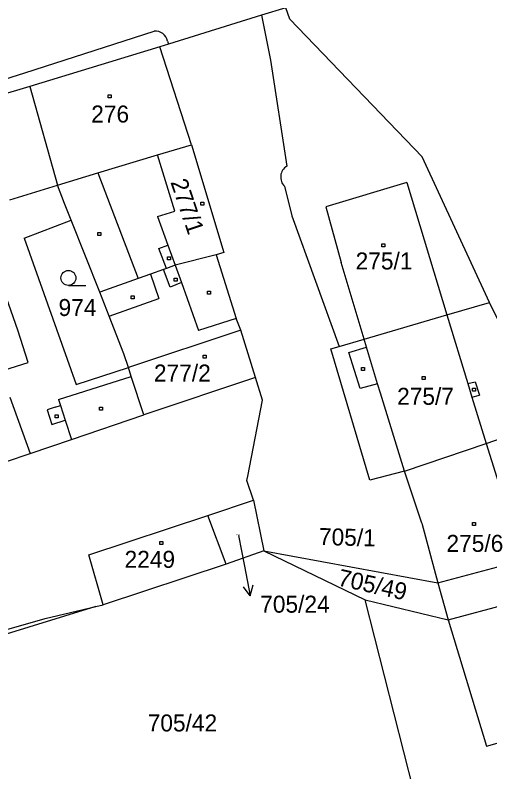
# Model space of a CAD drawing. Extents: x -711879 to -711361, y -1048782 to -1048177.
# Drawn here: x -711605.1 to -711557.6, y -1048600.7 to -1048524.9 of the extents above; entities that cross this region are included whole.
import ezdxf

# ---------------------------------------------------------------- set-up
doc = ezdxf.new("R2010")
doc.units = 0
for name, color, linetype in [('Vrstva 1', 7, 'Continuous'), ('Vrstva 13', 7, 'Continuous'), ('Vrstva 14', 7, 'Continuous'), ('Vrstva 15', 7, 'Continuous'), ('Vrstva 16', 7, 'Continuous'), ('Vrstva 2', 7, 'Continuous'), ('Vrstva 23', 7, 'Continuous'), ('Vrstva 25', 7, 'Continuous'), ('Vrstva 46', 7, 'Continuous')]:
    doc.layers.add(name, color=color, linetype=linetype)

msp = doc.modelspace()

# ---------------------------------------------------------------- linework, layer by layer
at = {"layer": 'Vrstva 1'}
for p, q in [((-711578.06, -1048524.2), (-711580.49, -1048524.94)), ((-711577.67, -1048525.33), (-711578.06, -1048524.2)), ((-711580.49, -1048524.94), (-711589.78, -1048527.84)), ((-711580.49, -1048524.94), (-711579.59, -1048529.44)), ((-711564.41, -1048539.14), (-711577.67, -1048525.33)), ((-711590.66, -1048528.12), (-711603.68, -1048532.09)), ((-711589.78, -1048527.84), (-711590.66, -1048528.12)), ((-711587.51, -1048537.93), (-711590.66, -1048528.12)), ((-711579.59, -1048529.44), (-711577.97, -1048540.06)), ((-711603.68, -1048532.09), (-711617, -1048536.1)), ((-711603.68, -1048532.09), (-711600.91, -1048541.96)), ((-711590.88, -1048538.94), (-711587.51, -1048537.93)), ((-711587.51, -1048537.93), (-711584.26, -1048548.7)), ((-711589.17, -1048544.57), (-711590.88, -1048538.94)), ((-711557.67, -1048553.71), (-711564.41, -1048539.14)), ((-711600.19, -1048543.79), (-711600.91, -1048541.96)), ((-711578.19, -1048542.07), (-711577.44, -1048545.04)), ((-711599.52, -1048545.48), (-711600.19, -1048543.79)), ((-711590.88, -1048545.1), (-711589.17, -1048544.57)), ((-711604.23, -1048547.27), (-711599.52, -1048545.48)), ((-711596.68, -1048552.69), (-711599.52, -1048545.48)), ((-711590.88, -1048545.1), (-711589.85, -1048547.97)), ((-711577.44, -1048545.04), (-711572.72, -1048558.11)), ((-711604.23, -1048547.27), (-711599.03, -1048561.92)), ((-711604.86, -1048556.48), (-711607.73, -1048548.39)), ((-711589.85, -1048547.97), (-711589.13, -1048549.98)), ((-711585.03, -1048548.93), (-711589.13, -1048549.98)), ((-711584.26, -1048548.7), (-711585.03, -1048548.93)), ((-711585.03, -1048548.93), (-711583.01, -1048555.3)), ((-711589.13, -1048549.98), (-711589.99, -1048550.29)), ((-711591.59, -1048550.86), (-711592.84, -1048551.31)), ((-711590.3, -1048550.4), (-711591.59, -1048550.86)), ((-711589.99, -1048550.29), (-711590.3, -1048550.4)), ((-711592.84, -1048551.31), (-711596.68, -1048552.69)), ((-711595.74, -1048555.07), (-711596.68, -1048552.69)), ((-711561.93, -1048554.95), (-711557.67, -1048553.71)), ((-711556.81, -1048555.48), (-711557.67, -1048553.71)), ((-711594.25, -1048558.85), (-711595.74, -1048555.07)), ((-711582.56, -1048556.49), (-711583.01, -1048555.3)), ((-711570.22, -1048557.38), (-711561.93, -1048554.95)), ((-711603.85, -1048559.72), (-711604.86, -1048556.48)), ((-711581.08, -1048561.22), (-711582.56, -1048556.49)), ((-711572.72, -1048558.11), (-711570.22, -1048557.38)), ((-711573.55, -1048558.36), (-711572.72, -1048558.11)), ((-711569.65, -1048571.51), (-711573.55, -1048558.36)), ((-711593.81, -1048560.21), (-711594.25, -1048558.85)), ((-711608.97, -1048561.32), (-711603.85, -1048559.72)), ((-711599.03, -1048561.92), (-711593.81, -1048560.21)), ((-711593.52, -1048561.12), (-711593.81, -1048560.21)), ((-711592.27, -1048564.95), (-711593.52, -1048561.12)), ((-711581.08, -1048561.22), (-711592.27, -1048564.95)), ((-711580.39, -1048563.48), (-711581.08, -1048561.22)), ((-711581.86, -1048571.1), (-711580.39, -1048563.48)), ((-711599.49, -1048567.41), (-711592.27, -1048564.95)), ((-711603.64, -1048568.82), (-711599.49, -1048567.41)), ((-711558, -1048567.81), (-711556.26, -1048567.22)), ((-711566.18, -1048570.58), (-711558, -1048567.81)), ((-711606.02, -1048569.63), (-711603.64, -1048568.82)), ((-711566.18, -1048570.58), (-711569.65, -1048571.51)), ((-711564.45, -1048575.81), (-711566.18, -1048570.58)), ((-711581.96, -1048571.52), (-711581.86, -1048571.1)), ((-711581.28, -1048573.5), (-711581.96, -1048571.52)), ((-711585.87, -1048575.02), (-711581.28, -1048573.5)), ((-711581.28, -1048573.5), (-711580.26, -1048578.57)), ((-711597.78, -1048578.97), (-711585.87, -1048575.02)), ((-711584.02, -1048579.9), (-711585.87, -1048575.02)), ((-711564.45, -1048575.81), (-711562.83, -1048581.76)), ((-711596.34, -1048583.99), (-711597.78, -1048578.97)), ((-711580.26, -1048578.57), (-711584.02, -1048579.9)), ((-711580.26, -1048578.57), (-711570.11, -1048583.49)), ((-711580.26, -1048578.57), (-711562.83, -1048581.76)), ((-711562.83, -1048581.76), (-711554.45, -1048579.51)), ((-711584.02, -1048579.9), (-711596.34, -1048583.99)), ((-711562.83, -1048581.76), (-711561.81, -1048585.49)), ((-711570.11, -1048583.49), (-711561.81, -1048585.49)), ((-711553.71, -1048647.83), (-711570.11, -1048583.49)), ((-711561.81, -1048585.49), (-711553.36, -1048583.2)), ((-711597.05, -1048584.15), (-711627.67, -1048593.58)), ((-711602.15, -1048585.34), (-711597.05, -1048584.15)), ((-711597.05, -1048584.15), (-711596.34, -1048583.99)), ((-711618.47, -1048589.99), (-711602.15, -1048585.34)), ((-711561.81, -1048585.49), (-711557.98, -1048598.11)), ((-711557.98, -1048598.11), (-711542.36, -1048593.72))]:
    msp.add_line(p, q, dxfattribs=at)
msp.add_arc((-711577.274, -1048541.153), 1.296, 122.47996, 225.0274, dxfattribs=at)
at = {"layer": 'Vrstva 13'}
msp.add_line((-711582.8, -1048577.03), (-711582.2, -1048580.12), dxfattribs=at)
at = {"layer": 'Vrstva 16'}
for p, q in [((-711582.2, -1048580.12), (-711581.623, -1048583.064)), ((-711581.623, -1048583.064), (-711581.325, -1048581.986)), ((-711581.623, -1048583.064), (-711582.306, -1048582.178))]:
    msp.add_line(p, q, dxfattribs=at)
at = {"layer": 'Vrstva 2'}
for p, q in [((-711604.16, -1048530.71), (-711591.22, -1048526.54)), ((-711589.88, -1048527.53), (-711589.78, -1048527.84)), ((-711617.42, -1048534.9), (-711604.16, -1048530.71)), ((-711596.86, -1048540.74), (-711590.88, -1048538.94)), ((-711600.91, -1048541.96), (-711596.86, -1048540.74)), ((-711596.86, -1048540.74), (-711592.84, -1048551.31)), ((-711565.95, -1048541.69), (-711574.05, -1048544.12)), ((-711565.95, -1048541.69), (-711561.93, -1048554.95)), ((-711605.68, -1048543.44), (-711600.91, -1048541.96)), ((-711574.05, -1048544.12), (-711572.53, -1048549.72)), ((-711590.75, -1048548.29), (-711589.85, -1048547.97)), ((-711589.99, -1048550.29), (-711590.75, -1048548.29)), ((-711589.13, -1048549.98), (-711588.5, -1048551.72)), ((-711570.22, -1048557.38), (-711572.53, -1048549.72)), ((-711591.59, -1048550.86), (-711590.77, -1048553.31)), ((-711589.64, -1048552.18), (-711590.3, -1048550.4)), ((-711588.5, -1048551.72), (-711589.64, -1048552.18)), ((-711588.5, -1048551.72), (-711586.79, -1048556.5)), ((-711595.74, -1048555.07), (-711590.77, -1048553.31)), ((-711583.01, -1048555.3), (-711586.79, -1048556.5)), ((-711561.93, -1048554.95), (-711559.84, -1048561.83)), ((-711582.56, -1048556.49), (-711593.81, -1048560.21)), ((-711569.98, -1048558.19), (-711570.22, -1048557.38)), ((-711571.74, -1048558.7), (-711569.98, -1048558.19)), ((-711568.88, -1048561.85), (-711569.98, -1048558.19)), ((-711570.6, -1048562.31), (-711571.74, -1048558.7)), ((-711600.81, -1048563.41), (-711593.52, -1048561.12)), ((-711568.88, -1048561.85), (-711570.6, -1048562.31)), ((-711568.59, -1048562.77), (-711568.88, -1048561.85)), ((-711559.84, -1048561.83), (-711559.1, -1048561.64)), ((-711559.84, -1048561.83), (-711559.43, -1048563.18)), ((-711559.1, -1048561.64), (-711558.69, -1048562.97)), ((-711566.98, -1048568), (-711568.59, -1048562.77)), ((-711559.43, -1048563.18), (-711558.69, -1048562.97)), ((-711605.66, -1048563.17), (-711603.64, -1048568.82)), ((-711600.81, -1048563.41), (-711600.61, -1048564.01)), ((-711559.43, -1048563.18), (-711558, -1048567.81)), ((-711601.14, -1048564.17), (-711601.95, -1048564.44)), ((-711601.95, -1048564.44), (-711601.47, -1048565.92)), ((-711601.14, -1048564.17), (-711600.61, -1048564.01)), ((-711600.61, -1048564.01), (-711600.12, -1048565.49)), ((-711601.47, -1048565.92), (-711600.12, -1048565.49)), ((-711600.12, -1048565.49), (-711599.49, -1048567.41)), ((-711566.18, -1048570.58), (-711566.98, -1048568)), ((-711558, -1048567.81), (-711556.25, -1048573.47))]:
    msp.add_line(p, q, dxfattribs=at)
msp.add_arc((-711591.143, -1048527.838), 1.3, 13.69049, 93.39509, dxfattribs=at)
at = {"layer": 'Vrstva 23'}
msp.add_line((-711599.81, -1048552), (-711598.06, -1048552), dxfattribs=at)
msp.add_circle((-711599.81, -1048551.25), 0.75, dxfattribs=at)
at = {"layer": 'Vrstva 25'}
for p, q in [((-711595.83, -1048532.91), (-711595.53, -1048532.91)), ((-711595.83, -1048533.21), (-711595.83, -1048532.91)), ((-711595.53, -1048533.21), (-711595.83, -1048533.21)), ((-711595.53, -1048532.91), (-711595.53, -1048533.21)), ((-711586.57, -1048543.66), (-711586.27, -1048543.66)), ((-711586.57, -1048543.96), (-711586.57, -1048543.66)), ((-711586.27, -1048543.96), (-711586.57, -1048543.96)), ((-711586.27, -1048543.66), (-711586.27, -1048543.96)), ((-711596.86, -1048546.7), (-711596.56, -1048546.7)), ((-711596.86, -1048547), (-711596.86, -1048546.7)), ((-711596.56, -1048547), (-711596.86, -1048547)), ((-711596.56, -1048546.7), (-711596.56, -1048547)), ((-711568.45, -1048547.83), (-711568.15, -1048547.83)), ((-711568.45, -1048548.13), (-711568.45, -1048547.83)), ((-711568.15, -1048547.83), (-711568.15, -1048548.13)), ((-711568.15, -1048548.13), (-711568.45, -1048548.13)), ((-711589.9, -1048549.12), (-711589.6, -1048549.12)), ((-711589.9, -1048549.42), (-711589.9, -1048549.12)), ((-711589.6, -1048549.42), (-711589.9, -1048549.42)), ((-711589.6, -1048549.12), (-711589.6, -1048549.42)), ((-711589.22, -1048551.28), (-711588.92, -1048551.28)), ((-711589.22, -1048551.58), (-711589.22, -1048551.28)), ((-711588.92, -1048551.58), (-711589.22, -1048551.58)), ((-711588.92, -1048551.28), (-711588.92, -1048551.58)), ((-711593.53, -1048553.05), (-711593.23, -1048553.05)), ((-711593.53, -1048553.35), (-711593.53, -1048553.05)), ((-711593.23, -1048553.05), (-711593.23, -1048553.35)), ((-711585.9, -1048552.57), (-711585.6, -1048552.57)), ((-711585.9, -1048552.87), (-711585.9, -1048552.57)), ((-711585.6, -1048552.87), (-711585.9, -1048552.87)), ((-711585.6, -1048552.57), (-711585.6, -1048552.87)), ((-711593.23, -1048553.35), (-711593.53, -1048553.35)), ((-711586.31, -1048558.98), (-711586.01, -1048558.98)), ((-711586.31, -1048559.28), (-711586.31, -1048558.98)), ((-711586.01, -1048559.28), (-711586.31, -1048559.28)), ((-711586.01, -1048558.98), (-711586.01, -1048559.28)), ((-711570.47, -1048560.21), (-711570.17, -1048560.21)), ((-711570.47, -1048560.51), (-711570.47, -1048560.21)), ((-711570.17, -1048560.51), (-711570.47, -1048560.51)), ((-711570.17, -1048560.21), (-711570.17, -1048560.51)), ((-711564.41, -1048561.12), (-711564.11, -1048561.12)), ((-711564.41, -1048561.42), (-711564.41, -1048561.12)), ((-711564.11, -1048561.42), (-711564.41, -1048561.42)), ((-711564.11, -1048561.12), (-711564.11, -1048561.42)), ((-711559.37, -1048562.29), (-711559.07, -1048562.29)), ((-711559.37, -1048562.59), (-711559.37, -1048562.29)), ((-711559.07, -1048562.29), (-711559.07, -1048562.59)), ((-711559.07, -1048562.59), (-711559.37, -1048562.59)), ((-711596.69, -1048564.2), (-711596.39, -1048564.2)), ((-711596.69, -1048564.5), (-711596.69, -1048564.2)), ((-711596.39, -1048564.5), (-711596.69, -1048564.5)), ((-711596.39, -1048564.2), (-711596.39, -1048564.5)), ((-711601.13, -1048564.95), (-711600.83, -1048564.95)), ((-711601.13, -1048565.25), (-711601.13, -1048564.95)), ((-711600.83, -1048565.25), (-711601.13, -1048565.25)), ((-711600.83, -1048564.95), (-711600.83, -1048565.25)), ((-711559.36, -1048575.72), (-711559.06, -1048575.72)), ((-711559.36, -1048576.02), (-711559.36, -1048575.72)), ((-711559.06, -1048575.72), (-711559.06, -1048576.02)), ((-711559.06, -1048576.02), (-711559.36, -1048576.02)), ((-711590.67, -1048577.63), (-711590.37, -1048577.63)), ((-711590.67, -1048577.93), (-711590.67, -1048577.63)), ((-711590.37, -1048577.93), (-711590.67, -1048577.93)), ((-711590.37, -1048577.63), (-711590.37, -1048577.93))]:
    msp.add_line(p, q, dxfattribs=at)
at = {"layer": 'Vrstva 46'}
for p, q in [((-711587.8, -1048527.22), (-711587.8, -1048527.22)), ((-711559.43, -1048563.18), (-711559.43, -1048563.18)), ((-711566.63, -1048569.12), (-711566.63, -1048569.12)), ((-711567.67, -1048570.98), (-711567.67, -1048570.98)), ((-711564.45, -1048575.81), (-711564.45, -1048575.81)), ((-711577.25, -1048580.03), (-711577.25, -1048580.03)), ((-711564.5, -1048581.45), (-711564.5, -1048581.45)), ((-711562.83, -1048581.76), (-711562.83, -1048581.76)), ((-711568.87, -1048588.34), (-711568.87, -1048588.34))]:
    msp.add_line(p, q, dxfattribs=at)

# ---------------------------------------------------------------- texts
at = {"layer": 'Vrstva 14'}
for s, height, p in [('974', 1.7, (-711600.8, -1048555.06)), ('705/24', 0.1, (-711583.052, -1048577.03)), ('705/42', 1.7, (-711591.878, -1048596.65))]:
    msp.add_text(s, height=height, dxfattribs=at).set_placement(p)
for s, rotation, p in [('705/1', 358.49538, (-711574.76, -1048577.98)), ('705/49', 347.41233, (-711572.944, -1048582.021))]:
    msp.add_text(s, height=1.7, rotation=rotation, dxfattribs=at).set_placement(p)
at = {"layer": 'Vrstva 15'}
for s, p in [('276', (-711597.53, -1048535.69)), ('275/1', (-711571.07, -1048550.4)), ('277/2', (-711591.253, -1048561.62)), ('275/7', (-711566.92, -1048563.95)), ('275/6', (-711561.98, -1048578.67)), ('2249', (-711594.192, -1048580.27))]:
    msp.add_text(s, height=1.7, dxfattribs=at).set_placement(p)
msp.add_text('277/1', height=1.7, rotation=288.59544, dxfattribs=at).set_placement((-711589.613, -1048541.647))
at = {"layer": 'Vrstva 16'}
msp.add_text('705/24', height=1.7, dxfattribs=at).set_placement((-711580.62, -1048584.76))

doc.saveas('drawing.dxf')
